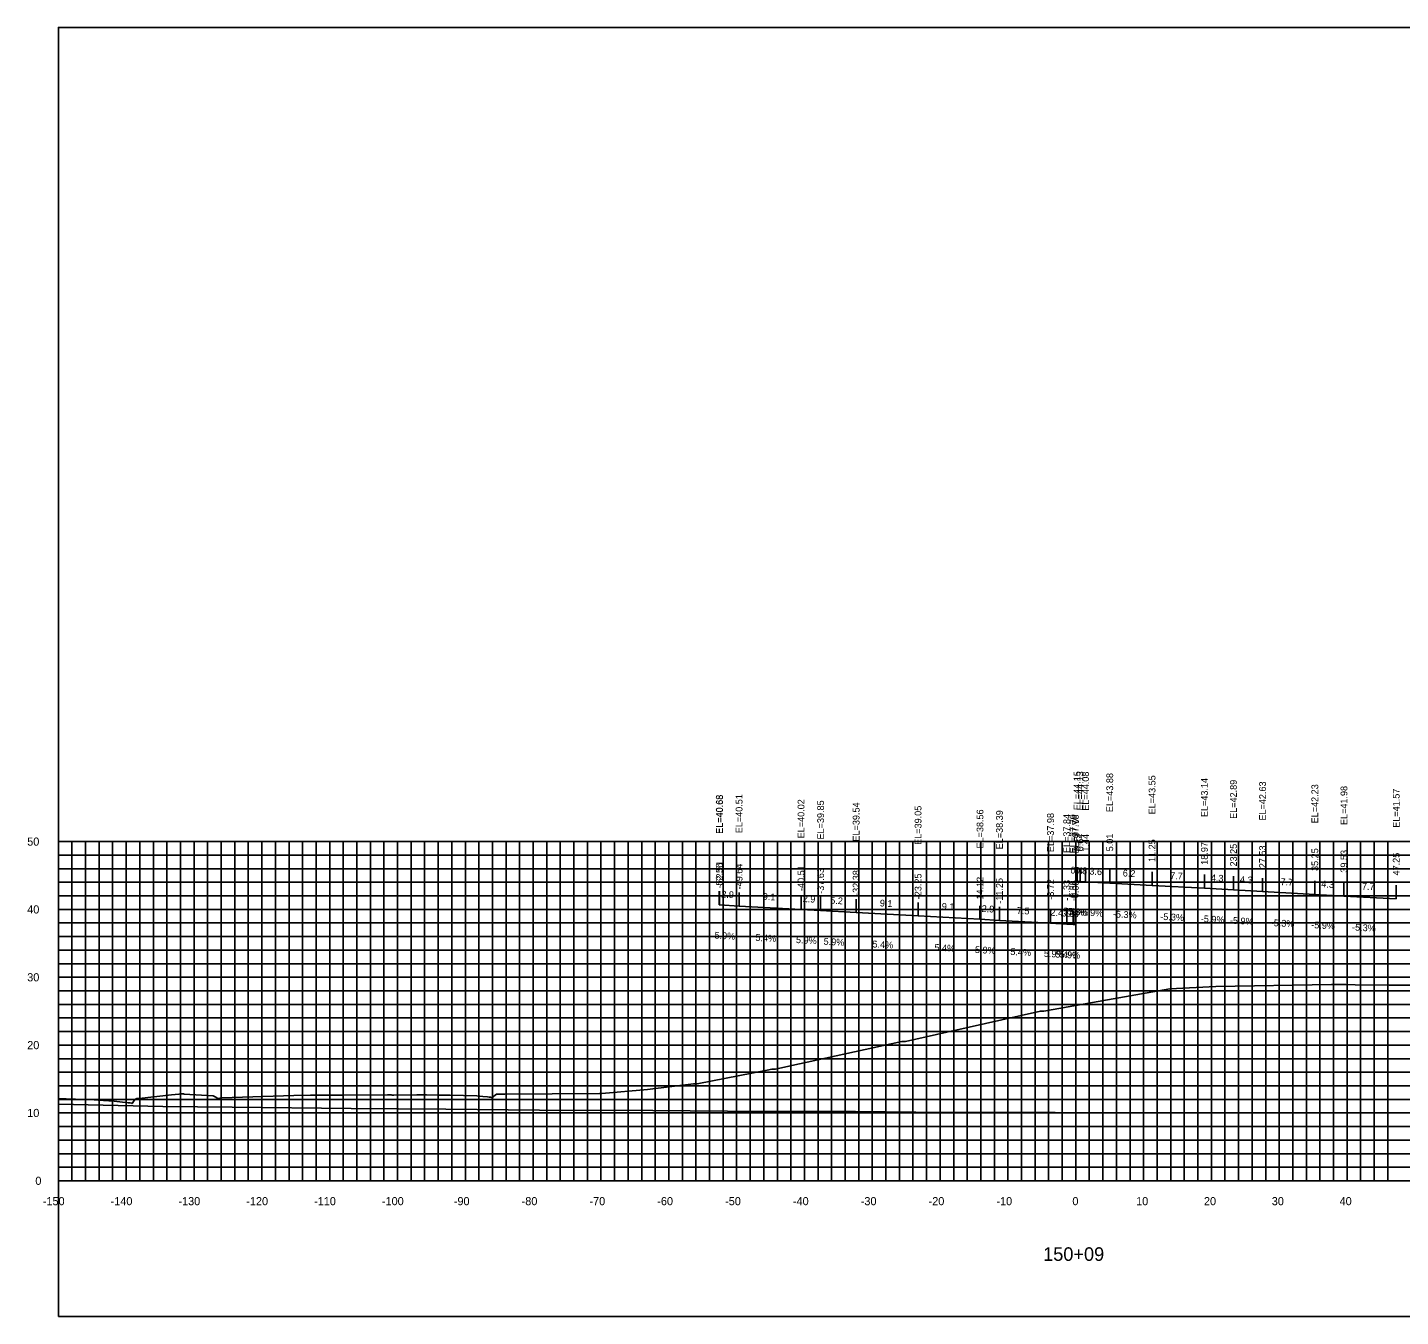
# Model space of a CAD drawing. Extents: x 1800880 to 1818864, y 245271 to 250560.
# Drawn here: x 1810955.8 to 1811158.2, y 248536.7 to 248726.7 of the extents above; entities that cross this region are included whole.
import ezdxf

# ---------------------------------------------------------------- set-up
doc = ezdxf.new("R2010")
doc.units = 0
for name, color, linetype in [('33', 7, 'Continuous'), ('ANNO-TXT', 7, 'Continuous'), ('AXIS', 7, 'Continuous'), ('CL-CNST', 7, 'Continuous'), ('DESIGN - DRAINAGE - Bridges', 7, 'Continuous'), ('Level 32', 7, 'Continuous'), ('Level 37', 7, 'Continuous'), ('Level 46', 7, 'Continuous'), ('Level 62', 7, 'Continuous'), ('SHT-BDR', 7, 'Continuous')]:
    doc.layers.add(name, color=color, linetype=linetype)

msp = doc.modelspace()

# ---------------------------------------------------------------- linework, layer by layer
at = {"layer": 'AXIS'}
msp.add_lwpolyline([(1811110.55, 248600.87), (1811111, 248600.84), (1811111.8, 248600.8), (1811115.37, 248600.59), (1811121.61, 248600.26), (1811129.33, 248599.85), (1811133.61, 248599.6), (1811137.9, 248599.35), (1811145.61, 248598.94), (1811149.9, 248598.69), (1811157.61, 248598.28)], dxfattribs=at)
at = {"layer": 'CL-CNST'}
msp.add_lwpolyline([(1810960.36, 248568.86), (1810960.38, 248568.86), (1810961.48, 248568.82), (1810965.64, 248568.65), (1810966.2, 248568.61), (1810968.6, 248568.45), (1810970.67, 248568.21), (1810970.85, 248568.22), (1810970.95, 248568.19), (1810971.15, 248568.14), (1810971.15, 248568.14), (1810971.21, 248568.12), (1810971.23, 248568.13), (1810971.63, 248568.68), (1810971.9, 248568.84), (1810972.27, 248568.85), (1810977.04, 248569.38), (1810978.14, 248569.49), (1810978.32, 248569.52), (1810978.33, 248569.52), (1810978.81, 248569.52), (1810978.92, 248569.51), (1810983.19, 248569.25), (1810983.46, 248569.09), (1810983.87, 248568.84), (1810984.42, 248568.96), (1810984.48, 248568.97), (1810995.08, 248569.27), (1810997.55, 248569.34), (1811000.69, 248569.35), (1811001.5, 248569.36), (1811001.71, 248569.36), (1811001.82, 248569.36), (1811002.01, 248569.36), (1811002.34, 248569.36), (1811008.86, 248569.4), (1811009.04, 248569.39), (1811009.18, 248569.38), (1811009.29, 248569.37), (1811009.39, 248569.37), (1811009.47, 248569.37), (1811009.54, 248569.36), (1811009.6, 248569.36), (1811009.65, 248569.36), (1811009.7, 248569.35), (1811009.74, 248569.35), (1811009.77, 248569.35), (1811009.81, 248569.35), (1811009.83, 248569.35), (1811013.2, 248569.39), (1811013.47, 248569.38), (1811013.51, 248569.38), (1811013.55, 248569.38), (1811013.62, 248569.38), (1811014.04, 248569.38), (1811014.12, 248569.38), (1811014.27, 248569.38), (1811014.61, 248569.37), (1811016.25, 248569.35), (1811018.11, 248569.32), (1811022.04, 248569.26), (1811022.93, 248569.16), (1811023.64, 248569.08), (1811023.86, 248569.06), (1811023.98, 248569.04), (1811024.04, 248569.04), (1811024.09, 248569.03), (1811024.12, 248569.03), (1811024.14, 248569.03), (1811024.16, 248569.02), (1811024.17, 248569.02), (1811024.18, 248569.02), (1811024.19, 248569.02), (1811024.2, 248569.02), (1811024.21, 248569.02), (1811024.22, 248569.02), (1811024.22, 248569.02), (1811024.23, 248569.02), (1811024.23, 248569.02), (1811024.23, 248569.02), (1811024.24, 248569.01), (1811024.24, 248569.01), (1811024.24, 248569.01), (1811024.25, 248569.01), (1811024.3, 248569.01), (1811024.31, 248569.01), (1811024.94, 248569.49), (1811024.97, 248569.51), (1811024.98, 248569.51), (1811025.03, 248569.51), (1811026.16, 248569.48), (1811040.14, 248569.59), (1811040.47, 248569.59), (1811047.24, 248570.19), (1811054.02, 248571.02), (1811054.44, 248571.02), (1811054.52, 248571.02), (1811064.84, 248573.04), (1811065.57, 248573.19), (1811065.71, 248573.19), (1811065.9, 248573.19), (1811066.07, 248573.19), (1811068.06, 248573.61), (1811084.7, 248577.25), (1811084.81, 248577.25), (1811085.15, 248577.24), (1811085.25, 248577.26), (1811091.33, 248578.65), (1811105.16, 248581.73), (1811105.32, 248581.73), (1811105.64, 248581.73), (1811115.04, 248583.39), (1811124.22, 248585), (1811131, 248585.36), (1811148.07, 248585.65), (1811148.57, 248585.65), (1811150.17, 248585.63), (1811151.56, 248585.62), (1811156.57, 248585.58), (1811160.93, 248585.55)], dxfattribs=at)
at = {"layer": 'DESIGN - DRAINAGE - Bridges'}
for p, q in [((1810960.3, 248606.72), (1810960.36, 248606.72)), ((1810960.36, 248556.72), (1810960.36, 248606.72)), ((1810960.3, 248596.72), (1810960.36, 248596.72)), ((1810960.3, 248586.72), (1810960.36, 248586.72)), ((1810960.3, 248576.72), (1810960.36, 248576.72)), ((1810960.3, 248566.72), (1810960.36, 248566.72)), ((1810960.3, 248556.72), (1810960.36, 248556.72)), ((1810960.36, 248556.72), (1811260.36, 248556.72)), ((1810960.36, 248556.66), (1810960.36, 248556.72)), ((1810970.36, 248556.66), (1810970.36, 248556.72)), ((1810980.36, 248556.66), (1810980.36, 248556.72)), ((1810990.36, 248556.66), (1810990.36, 248556.72)), ((1811000.36, 248556.66), (1811000.36, 248556.72)), ((1811010.36, 248556.66), (1811010.36, 248556.72)), ((1811020.36, 248556.66), (1811020.36, 248556.72)), ((1811030.36, 248556.66), (1811030.36, 248556.72)), ((1811040.36, 248556.66), (1811040.36, 248556.72)), ((1811050.36, 248556.66), (1811050.36, 248556.72)), ((1811060.36, 248556.66), (1811060.36, 248556.72)), ((1811070.36, 248556.66), (1811070.36, 248556.72)), ((1811080.36, 248556.66), (1811080.36, 248556.72)), ((1811090.36, 248556.66), (1811090.36, 248556.72)), ((1811100.36, 248556.66), (1811100.36, 248556.72)), ((1811110.36, 248556.66), (1811110.36, 248556.72)), ((1811120.36, 248556.66), (1811120.36, 248556.72)), ((1811130.36, 248556.66), (1811130.36, 248556.72)), ((1811140.36, 248556.66), (1811140.36, 248556.72)), ((1811150.36, 248556.66), (1811150.36, 248556.72))]:
    msp.add_line(p, q, dxfattribs=at)
at = {"layer": 'Level 37'}
for p, q in [((1811110.55, 248600.87), (1811110.55, 248602.87)), ((1811111, 248600.84), (1811111, 248602.84)), ((1811111.8, 248600.8), (1811111.8, 248602.8)), ((1811115.37, 248600.59), (1811115.37, 248602.59)), ((1811121.61, 248600.26), (1811121.61, 248602.26)), ((1811129.33, 248599.85), (1811129.33, 248601.85)), ((1811133.61, 248599.6), (1811133.61, 248601.6)), ((1811137.9, 248599.35), (1811137.9, 248601.35)), ((1811145.61, 248598.94), (1811145.61, 248600.94)), ((1811149.9, 248598.69), (1811149.9, 248600.69)), ((1811057.8, 248597.39), (1811057.8, 248599.39)), ((1811057.85, 248597.39), (1811057.85, 248599.39)), ((1811060.72, 248597.22), (1811060.72, 248599.22)), ((1811069.85, 248596.73), (1811069.85, 248598.73)), ((1811157.61, 248598.28), (1811157.61, 248600.28)), ((1811072.74, 248596.56), (1811072.74, 248598.56)), ((1811077.98, 248596.25), (1811077.98, 248598.25)), ((1811087.11, 248595.76), (1811087.11, 248597.76)), ((1811096.24, 248595.27), (1811096.24, 248597.27)), ((1811099.11, 248595.1), (1811099.11, 248597.1)), ((1811106.64, 248594.7), (1811106.64, 248596.7)), ((1811109.03, 248594.56), (1811109.03, 248596.56)), ((1811109.98, 248594.51), (1811109.98, 248596.51)), ((1811110.28, 248594.49), (1811110.28, 248596.49))]:
    msp.add_line(p, q, dxfattribs=at)
msp.add_lwpolyline([(1810960.36, 248536.72), (1811260.36, 248536.72), (1811260.36, 248726.72), (1810960.36, 248726.72)], close=True, dxfattribs=at)
at = {"layer": 'Level 46'}
for p, q in [((1810960.36, 248606.72), (1811260.36, 248606.72)), ((1810960.36, 248556.72), (1810960.36, 248606.72)), ((1810962.36, 248556.72), (1810962.36, 248606.72)), ((1810964.36, 248556.72), (1810964.36, 248606.72)), ((1810966.36, 248556.72), (1810966.36, 248606.72)), ((1810968.36, 248556.72), (1810968.36, 248606.72)), ((1810970.36, 248556.72), (1810970.36, 248606.72)), ((1810972.36, 248556.72), (1810972.36, 248606.72)), ((1810974.36, 248556.72), (1810974.36, 248606.72)), ((1810976.36, 248556.72), (1810976.36, 248606.72)), ((1810978.36, 248556.72), (1810978.36, 248606.72)), ((1810980.36, 248556.72), (1810980.36, 248606.72)), ((1810982.36, 248556.72), (1810982.36, 248606.72)), ((1810984.36, 248556.72), (1810984.36, 248606.72)), ((1810986.36, 248556.72), (1810986.36, 248606.72)), ((1810988.36, 248556.72), (1810988.36, 248606.72)), ((1810990.36, 248556.72), (1810990.36, 248606.72)), ((1810992.36, 248556.72), (1810992.36, 248606.72)), ((1810994.36, 248556.72), (1810994.36, 248606.72)), ((1810996.36, 248556.72), (1810996.36, 248606.72)), ((1810998.36, 248556.72), (1810998.36, 248606.72)), ((1811000.36, 248556.72), (1811000.36, 248606.72)), ((1811002.36, 248556.72), (1811002.36, 248606.72)), ((1811004.36, 248556.72), (1811004.36, 248606.72)), ((1811006.36, 248556.72), (1811006.36, 248606.72)), ((1811008.36, 248556.72), (1811008.36, 248606.72)), ((1811010.36, 248556.72), (1811010.36, 248606.72)), ((1811012.36, 248556.72), (1811012.36, 248606.72)), ((1811014.36, 248556.72), (1811014.36, 248606.72)), ((1811016.36, 248556.72), (1811016.36, 248606.72)), ((1811018.36, 248556.72), (1811018.36, 248606.72)), ((1811020.36, 248556.72), (1811020.36, 248606.72)), ((1811022.36, 248556.72), (1811022.36, 248606.72)), ((1811024.36, 248556.72), (1811024.36, 248606.72)), ((1811026.36, 248556.72), (1811026.36, 248606.72)), ((1811028.36, 248556.72), (1811028.36, 248606.72)), ((1811030.36, 248556.72), (1811030.36, 248606.72)), ((1811032.36, 248556.72), (1811032.36, 248606.72)), ((1811034.36, 248556.72), (1811034.36, 248606.72)), ((1811036.36, 248556.72), (1811036.36, 248606.72)), ((1811038.36, 248556.72), (1811038.36, 248606.72)), ((1811040.36, 248556.72), (1811040.36, 248606.72)), ((1811042.36, 248556.72), (1811042.36, 248606.72)), ((1811044.36, 248556.72), (1811044.36, 248606.72)), ((1811046.36, 248556.72), (1811046.36, 248606.72)), ((1811048.36, 248556.72), (1811048.36, 248606.72)), ((1811050.36, 248556.72), (1811050.36, 248606.72)), ((1811052.36, 248556.72), (1811052.36, 248606.72)), ((1811054.36, 248556.72), (1811054.36, 248606.72)), ((1811056.36, 248556.72), (1811056.36, 248606.72)), ((1811058.36, 248556.72), (1811058.36, 248606.72)), ((1811060.36, 248556.72), (1811060.36, 248606.72)), ((1811062.36, 248556.72), (1811062.36, 248606.72)), ((1811064.36, 248556.72), (1811064.36, 248606.72)), ((1811066.36, 248556.72), (1811066.36, 248606.72)), ((1811068.36, 248556.72), (1811068.36, 248606.72)), ((1811070.36, 248556.72), (1811070.36, 248606.72)), ((1811072.36, 248556.72), (1811072.36, 248606.72)), ((1811074.36, 248556.72), (1811074.36, 248606.72)), ((1811076.36, 248556.72), (1811076.36, 248606.72)), ((1811078.36, 248556.72), (1811078.36, 248606.72)), ((1811080.36, 248556.72), (1811080.36, 248606.72)), ((1811082.36, 248556.72), (1811082.36, 248606.72)), ((1811084.36, 248556.72), (1811084.36, 248606.72)), ((1811086.36, 248556.72), (1811086.36, 248606.72)), ((1811088.36, 248556.72), (1811088.36, 248606.72)), ((1811090.36, 248556.72), (1811090.36, 248606.72)), ((1811092.36, 248556.72), (1811092.36, 248606.72)), ((1811094.36, 248556.72), (1811094.36, 248606.72)), ((1811096.36, 248556.72), (1811096.36, 248606.72)), ((1811098.36, 248556.72), (1811098.36, 248606.72)), ((1811100.36, 248556.72), (1811100.36, 248606.72)), ((1811102.36, 248556.72), (1811102.36, 248606.72)), ((1811104.36, 248556.72), (1811104.36, 248606.72)), ((1811106.36, 248556.72), (1811106.36, 248606.72)), ((1811108.36, 248556.72), (1811108.36, 248606.72)), ((1811110.36, 248556.72), (1811110.36, 248606.72)), ((1811112.36, 248556.72), (1811112.36, 248606.72)), ((1811114.36, 248556.72), (1811114.36, 248606.72)), ((1811116.36, 248556.72), (1811116.36, 248606.72)), ((1811118.36, 248556.72), (1811118.36, 248606.72)), ((1811120.36, 248556.72), (1811120.36, 248606.72)), ((1811122.36, 248556.72), (1811122.36, 248606.72)), ((1811124.36, 248556.72), (1811124.36, 248606.72)), ((1811126.36, 248556.72), (1811126.36, 248606.72)), ((1811128.36, 248556.72), (1811128.36, 248606.72)), ((1811130.36, 248556.72), (1811130.36, 248606.72)), ((1811132.36, 248556.72), (1811132.36, 248606.72)), ((1811134.36, 248556.72), (1811134.36, 248606.72)), ((1811136.36, 248556.72), (1811136.36, 248606.72)), ((1811138.36, 248556.72), (1811138.36, 248606.72)), ((1811140.36, 248556.72), (1811140.36, 248606.72)), ((1811142.36, 248556.72), (1811142.36, 248606.72)), ((1811144.36, 248556.72), (1811144.36, 248606.72)), ((1811146.36, 248556.72), (1811146.36, 248606.72)), ((1811148.36, 248556.72), (1811148.36, 248606.72)), ((1811150.36, 248556.72), (1811150.36, 248606.72)), ((1811152.36, 248556.72), (1811152.36, 248606.72)), ((1811154.36, 248556.72), (1811154.36, 248606.72)), ((1811156.36, 248556.72), (1811156.36, 248606.72)), ((1810960.36, 248604.72), (1811260.36, 248604.72)), ((1810960.36, 248602.72), (1811260.36, 248602.72)), ((1810960.36, 248600.72), (1811260.36, 248600.72)), ((1810960.36, 248598.72), (1811260.36, 248598.72)), ((1810960.36, 248596.72), (1811260.36, 248596.72)), ((1810960.36, 248594.72), (1811260.36, 248594.72)), ((1810960.36, 248592.72), (1811260.36, 248592.72)), ((1810960.36, 248590.72), (1811260.36, 248590.72)), ((1810960.36, 248588.72), (1811260.36, 248588.72)), ((1810960.36, 248586.72), (1811260.36, 248586.72)), ((1810960.36, 248584.72), (1811260.36, 248584.72)), ((1810960.36, 248582.72), (1811260.36, 248582.72)), ((1810960.36, 248580.72), (1811260.36, 248580.72)), ((1810960.36, 248578.72), (1811260.36, 248578.72)), ((1810960.36, 248576.72), (1811260.36, 248576.72)), ((1810960.36, 248574.72), (1811260.36, 248574.72)), ((1810960.36, 248572.72), (1811260.36, 248572.72)), ((1810960.36, 248570.72), (1811260.36, 248570.72)), ((1810960.36, 248568.72), (1811260.36, 248568.72)), ((1810960.36, 248566.72), (1811260.36, 248566.72)), ((1810960.36, 248564.72), (1811260.36, 248564.72)), ((1810960.36, 248562.72), (1811260.36, 248562.72)), ((1810960.36, 248560.72), (1811260.36, 248560.72)), ((1810960.36, 248558.72), (1811260.36, 248558.72)), ((1810960.36, 248556.72), (1811260.36, 248556.72))]:
    msp.add_line(p, q, dxfattribs=at)
at = {"layer": 'Level 62'}
for points in [[(1811057.8, 248597.39), (1811057.85, 248597.39), (1811060.72, 248597.22), (1811069.85, 248596.73), (1811072.74, 248596.56), (1811077.98, 248596.25), (1811087.11, 248595.76), (1811096.24, 248595.27), (1811099.11, 248595.1), (1811106.64, 248594.7), (1811109.03, 248594.56), (1811109.98, 248594.51), (1811110.28, 248594.49)], [(1810960.36, 248568.02), (1810975.77, 248567.67), (1810985.99, 248567.59), (1811003.52, 248567.37), (1811017.5, 248567.28), (1811031.28, 248567.15), (1811048.02, 248567.07), (1811059.03, 248566.99), (1811077.9, 248566.92), (1811086.79, 248566.84), (1811107.33, 248566.81), (1811114.54, 248566.76), (1811136.45, 248566.76), (1811142.3, 248566.72), (1811165.33, 248566.75), (1811170.05, 248566.72), (1811194.04, 248566.79), (1811197.81, 248566.78), (1811222.6, 248566.9), (1811225.56, 248566.9), (1811251.05, 248567.05), (1811253.32, 248567.01), (1811260.36, 248567.05)]]:
    msp.add_lwpolyline(points, dxfattribs=at)

# ---------------------------------------------------------------- texts
for s, p in [('-150', (1810958.06, 248553.12)), ('-140', (1810968.06, 248553.12)), ('-130', (1810978.06, 248553.12)), ('-120', (1810988.06, 248553.12)), ('-110', (1810998.06, 248553.12)), ('-100', (1811008.06, 248553.12)), ('-90', (1811018.66, 248553.12)), ('-80', (1811028.66, 248553.12)), ('-70', (1811038.66, 248553.12)), ('-60', (1811048.66, 248553.12)), ('-50', (1811058.66, 248553.12)), ('-40', (1811068.66, 248553.12)), ('-30', (1811078.66, 248553.12)), ('-20', (1811088.66, 248553.12)), ('-10', (1811098.66, 248553.12)), ('0', (1811109.86, 248553.12)), ('10', (1811119.26, 248553.12)), ('20', (1811129.26, 248553.12)), ('30', (1811139.26, 248553.12)), ('40', (1811149.26, 248553.12))]:
    msp.add_text(s, height=1.2).set_placement(p)
at = {"layer": '33'}
for s, p in [('50', (1810955.76, 248606.12)), ('40', (1810955.76, 248596.12)), ('30', (1810955.76, 248586.12)), ('20', (1810955.76, 248576.12)), ('10', (1810955.76, 248566.12)), ('0', (1810956.96, 248556.12))]:
    msp.add_text(s, height=1.2, dxfattribs=at).set_placement(p)
at = {"layer": 'ANNO-TXT'}
for s, rotation, p in [('0.4', 356.6368, (1811109.56, 248602.03)), ('0.8', 356.9763, (1811110.18, 248601.99)), ('3.6', 356.6368, (1811112.35, 248601.87)), ('6.2', 356.9763, (1811117.27, 248601.59)), ('7.7', 356.9763, (1811124.25, 248601.22)), ('4.3', 356.6368, (1811130.25, 248600.9)), ('4.3', 356.6368, (1811134.54, 248600.65)), ('7.7', 356.9763, (1811140.53, 248600.31)), ('4.3', 356.6368, (1811146.54, 248599.99)), ('2.9', 356.6368, (1811058.07, 248598.48)), ('9.1', 356.9238, (1811064.19, 248598.14)), ('2.9', 356.6368, (1811070.08, 248597.82)), ('7.7', 356.9763, (1811152.53, 248599.65)), ('5.2', 356.6368, (1811074.14, 248597.58)), ('9.1', 356.9238, (1811081.45, 248597.17)), ('9.1', 356.9238, (1811090.58, 248596.68)), ('2.9', 356.6368, (1811096.46, 248596.36)), ('7.5', 356.9238, (1811101.65, 248596.07)), ('2.4', 356.6368, (1811106.62, 248595.8)), ('-5.9%', 356.6368, (1811108.08, 248596.01)), ('0.9', 356.9238, (1811108.28, 248595.7)), ('-5.3%', 356.9763, (1811108.73, 248595.96)), ('0.3', 356.6368, (1811108.91, 248595.67)), ('-5.9%', 356.6368, (1811110.89, 248595.85)), ('-5.3%', 356.9763, (1811115.82, 248595.56)), ('-5.3%', 356.9763, (1811122.8, 248595.19)), ('-5.9%', 356.6368, (1811128.77, 248594.88)), ('-5.9%', 356.6368, (1811133.06, 248594.63)), ('-5.3%', 356.9763, (1811139.08, 248594.28)), ('-5.9%', 356.6368, (1811145.06, 248593.97)), ('5.9%', 356.6368, (1811057.08, 248592.43)), ('5.4%', 356.9238, (1811063.11, 248592.09)), ('5.9%', 356.6368, (1811069.09, 248591.77)), ('-5.3%', 356.9763, (1811151.08, 248593.62)), ('5.9%', 356.6368, (1811073.16, 248591.53)), ('5.4%', 356.9238, (1811080.37, 248591.12)), ('5.4%', 356.9238, (1811089.5, 248590.63)), ('5.9%', 356.6368, (1811095.47, 248590.31)), ('5.4%', 356.9238, (1811100.7, 248590.01)), ('5.9%', 356.6368, (1811105.63, 248589.75)), ('5.4%', 356.9238, (1811107.33, 248589.64)), ('5.9%', 356.6368, (1811107.93, 248589.62))]:
    msp.add_text(s, height=1, rotation=rotation, dxfattribs=at).set_placement(p)
at = {"layer": 'DESIGN - DRAINAGE - Bridges'}
for s, height, p in [('>', 1.5, (1811109.75, 248608.97)), ('-', 0.0001, (1810960.36, 248556.72))]:
    msp.add_text(s, height=height, dxfattribs=at).set_placement(p)
at = {"layer": 'Level 32'}
msp.add_text('150+09', height=2, dxfattribs=at).set_placement((1811105.55, 248544.92))
at = {"layer": 'SHT-BDR'}
for s, p in [('EL=44.15', (1811111.05, 248611.34)), ('EL=44.13', (1811111.5, 248611.31)), ('EL=44.08', (1811112.3, 248611.27)), ('EL=43.88', (1811115.87, 248611.06)), ('EL=43.55', (1811122.11, 248610.73)), ('EL=43.14', (1811129.83, 248610.33)), ('EL=42.89', (1811134.11, 248610.07)), ('EL=42.63', (1811138.4, 248609.82)), ('EL=42.23', (1811146.11, 248609.41)), ('EL=41.98', (1811150.4, 248609.16)), ('EL=40.68', (1811058.3, 248607.87)), ('EL=40.68', (1811058.35, 248607.86)), ('EL=40.51', (1811061.22, 248607.95)), ('EL=40.02', (1811070.35, 248607.2)), ('EL=41.57', (1811158.11, 248608.76)), ('EL=39.85', (1811073.24, 248607.03)), ('EL=39.54', (1811078.48, 248606.73)), ('EL=39.05', (1811087.61, 248606.24)), ('EL=38.56', (1811096.74, 248605.7)), ('EL=38.39', (1811099.61, 248605.58)), ('EL=37.98', (1811107.14, 248605.17)), ('EL=37.84', (1811109.53, 248605.03)), ('EL=37.79', (1811110.48, 248604.98)), ('EL=37.78', (1811110.78, 248604.96)), ('0.19', (1811111.05, 248605.31)), ('0.64', (1811111.5, 248605.28)), ('1.44', (1811112.3, 248605.24)), ('5.01', (1811115.87, 248605.28)), ('11.25', (1811122.11, 248603.71)), ('18.97', (1811129.83, 248603.3)), ('23.25', (1811134.11, 248603.05)), ('27.53', (1811138.4, 248602.8)), ('35.25', (1811146.11, 248602.39)), ('39.53', (1811150.4, 248602.14)), ('47.25', (1811158.11, 248601.73)), ('-52.56', (1811058.3, 248599.8)), ('-52.51', (1811058.35, 248600.1)), ('-49.64', (1811061.22, 248599.68)), ('-40.51', (1811070.35, 248599.44)), ('-37.63', (1811073.24, 248599.02)), ('-32.38', (1811078.48, 248598.71)), ('-23.25', (1811087.61, 248598.22)), ('-14.12', (1811096.74, 248597.73)), ('-11.25', (1811099.61, 248597.56)), ('-3.72', (1811107.14, 248598.15)), ('-1.33', (1811109.53, 248598.01)), ('-0.38', (1811110.48, 248597.96)), ('-0.08', (1811110.78, 248597.94))]:
    msp.add_text(s, height=1, rotation=90, dxfattribs=at).set_placement(p)

doc.saveas('drawing.dxf')
